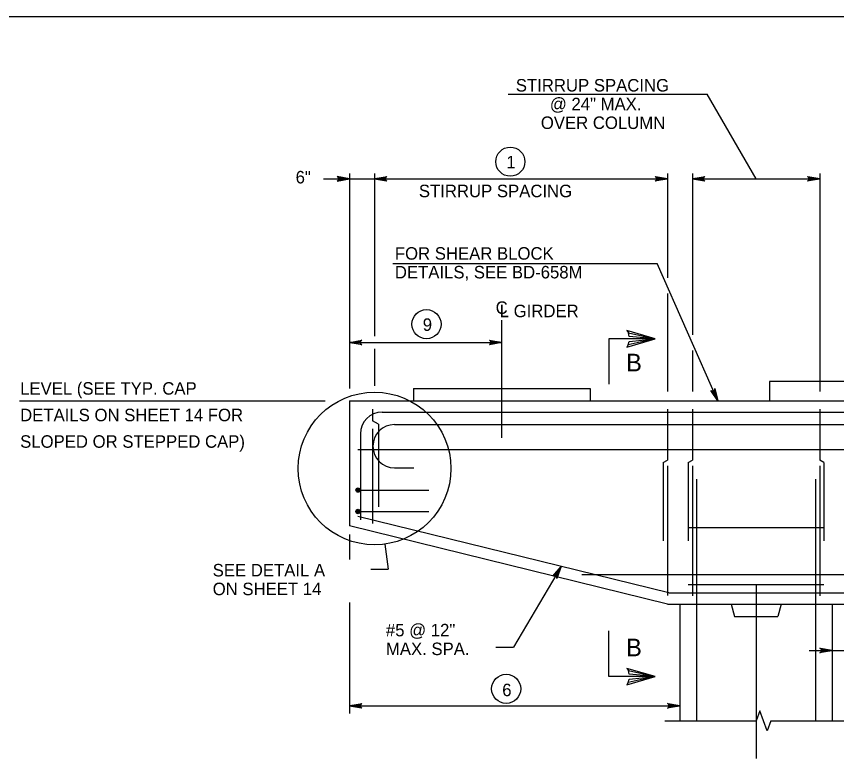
# Model space of a CAD drawing. Extents: x 646165 to 651486, y 296916 to 299292.
# Drawn here: x 648397.7 to 648594.6, y 298505 to 298683.3 of the extents above; entities that cross this region are included whole.
import ezdxf

# ---------------------------------------------------------------- set-up
doc = ezdxf.new("R2010")
doc.units = 0
for name, color, linetype in [('1', 7, 'Continuous'), ('2', 7, 'Continuous'), ('50', 7, 'Continuous'), ('51', 7, 'Continuous'), ('52', 7, 'Continuous'), ('53', 7, 'Continuous'), ('54', 7, 'Continuous')]:
    doc.layers.add(name, color=color, linetype=linetype)

msp = doc.modelspace()

# ---------------------------------------------------------------- linework, layer by layer
at = {"layer": '1'}
for p, q in [((648539.93, 298605.84), (648539.93, 298594.91)), ((648551, 298605.84), (648539.93, 298605.84)), ((648539.93, 298524.73), (648539.93, 298535.66)), ((648551, 298524.73), (648539.93, 298524.73))]:
    msp.add_line(p, q, dxfattribs=at)
for points in [[(648544.58, 298604.36), (648544.82, 298605.21), (648551, 298605.84), (648544.58, 298604.36), (648544.25, 298603.85), (648551, 298605.84), (648544.82, 298606.39), (648544.6, 298607.23), (648551, 298605.84), (648544.25, 298607.79), (648544.6, 298607.23)], [(648544.58, 298523.26), (648544.82, 298524.11), (648551, 298524.73), (648544.58, 298523.26), (648544.25, 298522.75), (648551, 298524.73), (648544.82, 298525.29), (648544.6, 298526.13), (648551, 298524.73), (648544.25, 298526.68), (648544.6, 298526.13)]]:
    msp.add_lwpolyline(points, dxfattribs=at)
at = {"layer": '2'}
msp.add_line((648147.59, 298683.25), (648933.59, 298683.25), dxfattribs=at)
at = {"layer": '50'}
for p, q in [((648514.22, 298582.07), (648514.22, 298610.33)), ((648575.26, 298546.9), (648575.26, 298505.01))]:
    msp.add_line(p, q, dxfattribs=at)
at = {"layer": '51'}
for p, q in [((648578.44, 298595.61), (648578.44, 298590.91)), ((648620.84, 298595.61), (648578.44, 298595.61)), ((648493.02, 298593.91), (648493.02, 298590.91)), ((648493.02, 298593.91), (648535.42, 298593.91)), ((648535.42, 298593.91), (648535.42, 298590.91)), ((648477.66, 298590.91), (648896.65, 298590.91)), ((648477.66, 298590.91), (648477.66, 298560.91)), ((648553.98, 298542.11), (648477.66, 298560.91)), ((648553.98, 298542.11), (648896.65, 298542.11)), ((648556.98, 298542.11), (648556.98, 298514.09)), ((648569.26, 298542.11), (648570.04, 298539.11)), ((648581.26, 298542.11), (648580.49, 298539.11)), ((648593.54, 298542.11), (648593.54, 298514.09)), ((648570.04, 298539.11), (648580.49, 298539.11))]:
    msp.add_line(p, q, dxfattribs=at)
at = {"layer": '52'}
for p, q in [((648515.72, 298664.61), (648563.5, 298664.61)), ((648575.26, 298644.24), (648563.5, 298664.61)), ((648471.42, 298644.24), (648553.98, 298644.24)), ((648477.66, 298645.56), (648477.66, 298593.92)), ((648483.66, 298645.56), (648483.66, 298606.43)), ((648553.98, 298645.56), (648553.98, 298620.46)), ((648559.98, 298645.56), (648559.98, 298606.75)), ((648559.98, 298644.24), (648590.54, 298644.24)), ((648590.54, 298645.56), (648590.54, 298593.17)), ((648488.1, 298623.9), (648551.55, 298623.9)), ((648566.07, 298590.91), (648551.55, 298623.9)), ((648553.98, 298616.69), (648553.98, 298593.17)), ((648477.66, 298604.96), (648514.22, 298604.96)), ((648483.66, 298603.45), (648483.66, 298594.53)), ((648559.98, 298602.98), (648559.98, 298593.17)), ((648398.52, 298590.91), (648471.84, 298590.91)), ((648477.66, 298558.81), (648477.66, 298552.79)), ((648486.17, 298556.53), (648486.99, 298550.52)), ((648528.5, 298551.14), (648517, 298531.76)), ((648482.79, 298550.52), (648486.99, 298550.52)), ((648477.66, 298542.5), (648477.66, 298515.85)), ((648512.8, 298531.76), (648517, 298531.76)), ((648588.01, 298531.01), (648620.82, 298531.01)), ((648477.66, 298517.65), (648556.98, 298517.65)), ((648553.34, 298514.09), (648575.26, 298514.09)), ((648578.76, 298514.09), (648597.33, 298514.09))]:
    msp.add_line(p, q, dxfattribs=at)
for points in [[(648477.66, 298644.24), (648474.68, 298644.8), (648474.8, 298644.72), (648474.91, 298644.64), (648474.97, 298644.54), (648475.03, 298644.44), (648475.05, 298644.34), (648475.06, 298644.24), (648475.05, 298644.14), (648475.03, 298644.04), (648474.97, 298643.94), (648474.91, 298643.84), (648474.8, 298643.76), (648474.68, 298643.68), (648477.66, 298644.24), (648474.8, 298643.76), (648474.91, 298643.84), (648477.66, 298644.24), (648474.97, 298643.94), (648475.03, 298644.04), (648477.66, 298644.24), (648475.05, 298644.14), (648475.06, 298644.24), (648477.66, 298644.24), (648475.05, 298644.34), (648475.03, 298644.44), (648477.66, 298644.24), (648474.97, 298644.54), (648474.91, 298644.64), (648477.66, 298644.24), (648474.8, 298644.72)], [(648483.66, 298644.24), (648486.65, 298644.8), (648486.53, 298644.72), (648486.42, 298644.64), (648486.36, 298644.54), (648486.3, 298644.44), (648486.28, 298644.34), (648486.26, 298644.24), (648486.28, 298644.14), (648486.3, 298644.04), (648486.36, 298643.94), (648486.42, 298643.84), (648486.53, 298643.76), (648486.65, 298643.68), (648483.66, 298644.24), (648486.53, 298643.76), (648486.42, 298643.84), (648483.66, 298644.24), (648486.36, 298643.94), (648486.3, 298644.04), (648483.66, 298644.24), (648486.28, 298644.14), (648486.26, 298644.24), (648483.66, 298644.24), (648486.28, 298644.34), (648486.3, 298644.44), (648483.66, 298644.24), (648486.36, 298644.54), (648486.42, 298644.64), (648483.66, 298644.24), (648486.53, 298644.72)], [(648553.98, 298644.24), (648551, 298643.68), (648551.12, 298643.76), (648551.23, 298643.84), (648551.29, 298643.94), (648551.35, 298644.04), (648551.37, 298644.14), (648551.38, 298644.24), (648551.37, 298644.34), (648551.35, 298644.44), (648551.29, 298644.54), (648551.23, 298644.64), (648551.12, 298644.72), (648551, 298644.8), (648553.98, 298644.24), (648551.12, 298644.72), (648551.23, 298644.64), (648553.98, 298644.24), (648551.29, 298644.54), (648551.35, 298644.44), (648553.98, 298644.24), (648551.37, 298644.34), (648551.38, 298644.24), (648553.98, 298644.24), (648551.37, 298644.14), (648551.35, 298644.04), (648553.98, 298644.24), (648551.29, 298643.94), (648551.23, 298643.84), (648553.98, 298644.24), (648551.12, 298643.76)], [(648559.98, 298644.24), (648562.97, 298644.8), (648562.85, 298644.72), (648562.74, 298644.64), (648562.68, 298644.54), (648562.62, 298644.44), (648562.6, 298644.34), (648562.58, 298644.24), (648562.6, 298644.14), (648562.62, 298644.04), (648562.68, 298643.94), (648562.74, 298643.84), (648562.85, 298643.76), (648562.97, 298643.68), (648559.98, 298644.24), (648562.85, 298643.76), (648562.74, 298643.84), (648559.98, 298644.24), (648562.68, 298643.94), (648562.62, 298644.04), (648559.98, 298644.24), (648562.6, 298644.14), (648562.58, 298644.24), (648559.98, 298644.24), (648562.6, 298644.34), (648562.62, 298644.44), (648559.98, 298644.24), (648562.68, 298644.54), (648562.74, 298644.64), (648559.98, 298644.24), (648562.85, 298644.72)], [(648590.54, 298644.24), (648587.56, 298643.68), (648587.68, 298643.76), (648587.79, 298643.84), (648587.85, 298643.94), (648587.91, 298644.04), (648587.93, 298644.14), (648587.94, 298644.24), (648587.93, 298644.34), (648587.91, 298644.44), (648587.85, 298644.54), (648587.79, 298644.64), (648587.68, 298644.72), (648587.56, 298644.8), (648590.54, 298644.24), (648587.68, 298644.72), (648587.79, 298644.64), (648590.54, 298644.24), (648587.85, 298644.54), (648587.91, 298644.44), (648590.54, 298644.24), (648587.93, 298644.34), (648587.94, 298644.24), (648590.54, 298644.24), (648587.93, 298644.14), (648587.91, 298644.04), (648590.54, 298644.24), (648587.85, 298643.94), (648587.79, 298643.84), (648590.54, 298644.24), (648587.68, 298643.76)], [(648477.66, 298604.96), (648480.65, 298605.52), (648480.42, 298605.36), (648480.3, 298605.16), (648480.26, 298604.96), (648480.3, 298604.76), (648480.42, 298604.56), (648480.65, 298604.4), (648477.66, 298604.96), (648480.42, 298604.56), (648480.3, 298604.76), (648477.66, 298604.96), (648480.26, 298604.96), (648480.3, 298605.16), (648477.66, 298604.96), (648480.42, 298605.36)], [(648514.22, 298604.96), (648511.24, 298604.4), (648511.47, 298604.56), (648511.59, 298604.76), (648511.62, 298604.96), (648511.59, 298605.16), (648511.47, 298605.36), (648511.24, 298605.52), (648514.22, 298604.96), (648511.47, 298605.36), (648511.59, 298605.16), (648514.22, 298604.96), (648511.62, 298604.96), (648511.59, 298604.76), (648514.22, 298604.96), (648511.47, 298604.56)], [(648566.07, 298590.91), (648564.36, 298593.41), (648564.48, 298593.34), (648564.6, 298593.27), (648564.71, 298593.25), (648564.83, 298593.24), (648564.92, 298593.26), (648565.02, 298593.29), (648565.11, 298593.34), (648565.19, 298593.4), (648565.26, 298593.49), (648565.33, 298593.59), (648565.35, 298593.73), (648565.38, 298593.86), (648566.07, 298590.91), (648565.35, 298593.73), (648565.33, 298593.59), (648566.07, 298590.91), (648565.26, 298593.49), (648565.19, 298593.4), (648566.07, 298590.91), (648565.11, 298593.34), (648565.02, 298593.29), (648566.07, 298590.91), (648564.92, 298593.26), (648564.83, 298593.24), (648566.07, 298590.91), (648564.71, 298593.25), (648564.6, 298593.27), (648566.07, 298590.91), (648564.48, 298593.34)], [(648528.5, 298551.14), (648527.46, 298548.29), (648527.45, 298548.43), (648527.44, 298548.57), (648527.38, 298548.67), (648527.33, 298548.78), (648527.25, 298548.84), (648527.17, 298548.91), (648527.08, 298548.94), (648526.98, 298548.98), (648526.87, 298548.98), (648526.75, 298548.98), (648526.62, 298548.92), (648526.5, 298548.86), (648528.5, 298551.14), (648526.62, 298548.92), (648526.75, 298548.98), (648528.5, 298551.14), (648526.87, 298548.98), (648526.98, 298548.98), (648528.5, 298551.14), (648527.08, 298548.94), (648527.17, 298548.91), (648528.5, 298551.14), (648527.25, 298548.84), (648527.33, 298548.78), (648528.5, 298551.14), (648527.38, 298548.67), (648527.44, 298548.57), (648528.5, 298551.14), (648527.45, 298548.43)], [(648593.54, 298531.01), (648590.56, 298530.45), (648590.68, 298530.53), (648590.79, 298530.61), (648590.85, 298530.71), (648590.91, 298530.81), (648590.93, 298530.91), (648590.94, 298531.01), (648590.93, 298531.11), (648590.91, 298531.21), (648590.85, 298531.31), (648590.79, 298531.41), (648590.68, 298531.49), (648590.56, 298531.57), (648593.54, 298531.01), (648590.68, 298531.49), (648590.79, 298531.41), (648593.54, 298531.01), (648590.85, 298531.31), (648590.91, 298531.21), (648593.54, 298531.01), (648590.93, 298531.11), (648590.94, 298531.01), (648593.54, 298531.01), (648590.93, 298530.91), (648590.91, 298530.81), (648593.54, 298531.01), (648590.85, 298530.71), (648590.79, 298530.61), (648593.54, 298531.01), (648590.68, 298530.53)], [(648477.66, 298517.65), (648480.65, 298518.21), (648480.53, 298518.13), (648480.42, 298518.05), (648480.36, 298517.95), (648480.3, 298517.85), (648480.28, 298517.75), (648480.26, 298517.65), (648480.28, 298517.55), (648480.3, 298517.45), (648480.36, 298517.35), (648480.42, 298517.25), (648480.53, 298517.17), (648480.65, 298517.09), (648477.66, 298517.65), (648480.53, 298517.17), (648480.42, 298517.25), (648477.66, 298517.65), (648480.36, 298517.35), (648480.3, 298517.45), (648477.66, 298517.65), (648480.28, 298517.55), (648480.26, 298517.65), (648477.66, 298517.65), (648480.28, 298517.75), (648480.3, 298517.85), (648477.66, 298517.65), (648480.36, 298517.95), (648480.42, 298518.05), (648477.66, 298517.65), (648480.53, 298518.13)], [(648556.98, 298517.65), (648554, 298517.09), (648554.12, 298517.17), (648554.23, 298517.25), (648554.29, 298517.35), (648554.35, 298517.45), (648554.37, 298517.55), (648554.38, 298517.65), (648554.37, 298517.75), (648554.35, 298517.85), (648554.29, 298517.95), (648554.23, 298518.05), (648554.12, 298518.13), (648554, 298518.21), (648556.98, 298517.65), (648554.12, 298518.13), (648554.23, 298518.05), (648556.98, 298517.65), (648554.29, 298517.95), (648554.35, 298517.85), (648556.98, 298517.65), (648554.37, 298517.75), (648554.38, 298517.65), (648556.98, 298517.65), (648554.37, 298517.55), (648554.35, 298517.45), (648556.98, 298517.65), (648554.29, 298517.35), (648554.23, 298517.25), (648556.98, 298517.65), (648554.12, 298517.17)], [(648578.76, 298514.09), (648577.88, 298511.68), (648576.13, 298516.49), (648575.26, 298514.09)]]:
    msp.add_lwpolyline(points, dxfattribs=at)
for centre, radius in [((648516.27, 298648.36), 3.5), ((648496.15, 298609.33), 3.5), ((648483.69, 298574.69), 18.33), ((648515.28, 298521.77), 3.5)]:
    msp.add_circle(centre, radius, dxfattribs=at)
at = {"layer": '54'}
for p, q in [((648483.19, 298588.91), (648483.19, 298586.16)), ((648553.98, 298588.91), (648553.98, 298576.71)), ((648559.98, 298588.91), (648559.98, 298576.71)), ((648590.54, 298588.91), (648590.54, 298576.71)), ((648485.5, 298588.23), (648722.66, 298588.23)), ((648484.66, 298585.31), (648483.19, 298586.16)), ((648484.66, 298585.31), (648484.66, 298565.49)), ((648488.5, 298585.23), (648817.86, 298585.23)), ((648480.3, 298583.03), (648480.3, 298562.32)), ((648483.19, 298584.18), (648483.19, 298561.49)), ((648479.66, 298579.23), (648896.65, 298579.23)), ((648552.98, 298576.14), (648553.98, 298576.71)), ((648558.98, 298576.14), (648559.98, 298576.71)), ((648591.54, 298576.14), (648590.54, 298576.71)), ((648488.5, 298574.83), (648493.14, 298574.83)), ((648552.98, 298576.14), (648552.98, 298557.34)), ((648553.98, 298575.3), (648553.98, 298544.17)), ((648558.98, 298576.14), (648558.98, 298557.34)), ((648559.98, 298575.3), (648559.98, 298544.11)), ((648590.54, 298575.3), (648590.54, 298544.11)), ((648591.54, 298576.14), (648591.54, 298557.34)), ((648560.98, 298572.11), (648560.98, 298514.09)), ((648589.54, 298572.11), (648589.54, 298514.09)), ((648479.75, 298569.5), (648496.73, 298569.5)), ((648554.31, 298544.79), (648479.66, 298563.17)), ((648479.75, 298564.35), (648496.73, 298564.35)), ((648558.98, 298560.48), (648591.54, 298560.48)), ((648533.44, 298549.23), (648896.65, 298549.23)), ((648558.98, 298546.79), (648591.54, 298546.79)), ((648554.31, 298544.79), (648620.82, 298544.79))]:
    msp.add_line(p, q, dxfattribs=at)
for centre, radius in [((648479.75, 298569.5), 0.533), ((648479.75, 298569.5), 0.4), ((648479.75, 298569.5), 0.267), ((648479.75, 298569.5), 0.133), ((648479.75, 298564.35), 0.533), ((648479.75, 298564.35), 0.4), ((648479.75, 298564.35), 0.267), ((648479.75, 298564.35), 0.133)]:
    msp.add_circle(centre, radius, dxfattribs=at)
for centre, end in [((648485.5, 298583.03), 180), ((648488.5, 298580.03), 270)]:
    msp.add_arc(centre, 5.2, 90, end, dxfattribs=at)

# ---------------------------------------------------------------- texts
at = {"layer": '1'}
for p in [(648544.06, 298598), (648544.06, 298529.59)]:
    msp.add_text('B', height=4.23, dxfattribs=at).set_placement(p)
at = {"layer": '53'}
for s, p in [('STIRRUP SPACING', (648517.59, 298665.21)), ('@ 24" MAX.', (648525.76, 298660.71)), ('OVER COLUMN', (648523.59, 298656.21)), ('1', (648515.31, 298646.75)), ('6"', (648464.75, 298643.14)), ('STIRRUP SPACING', (648494.33, 298639.83)), ('FOR SHEAR BLOCK', (648488.56, 298624.83)), ('DETAILS, SEE BD-658M', (648488.56, 298620.33)), ('C', (648512.75, 298611.81)), ('L GIRDER', (648513.73, 298611.01)), ('9', (648495.26, 298607.73)), ('LEVEL (SEE TYP. CAP', (648398.64, 298592.41)), ('DETAILS ON SHEET 14 FOR', (648398.64, 298586.03)), ('SLOPED OR STEPPED CAP)', (648398.64, 298579.66)), ('SEE DETAIL A', (648444.85, 298548.76)), ('ON SHEET 14', (648444.85, 298544.26)), ('#5 @ 12"', (648486.42, 298534.37)), ('MAX. SPA.', (648486.42, 298529.87)), ('6', (648514.33, 298520))]:
    msp.add_text(s, height=3, dxfattribs=at).set_placement(p)

doc.saveas('drawing.dxf')
